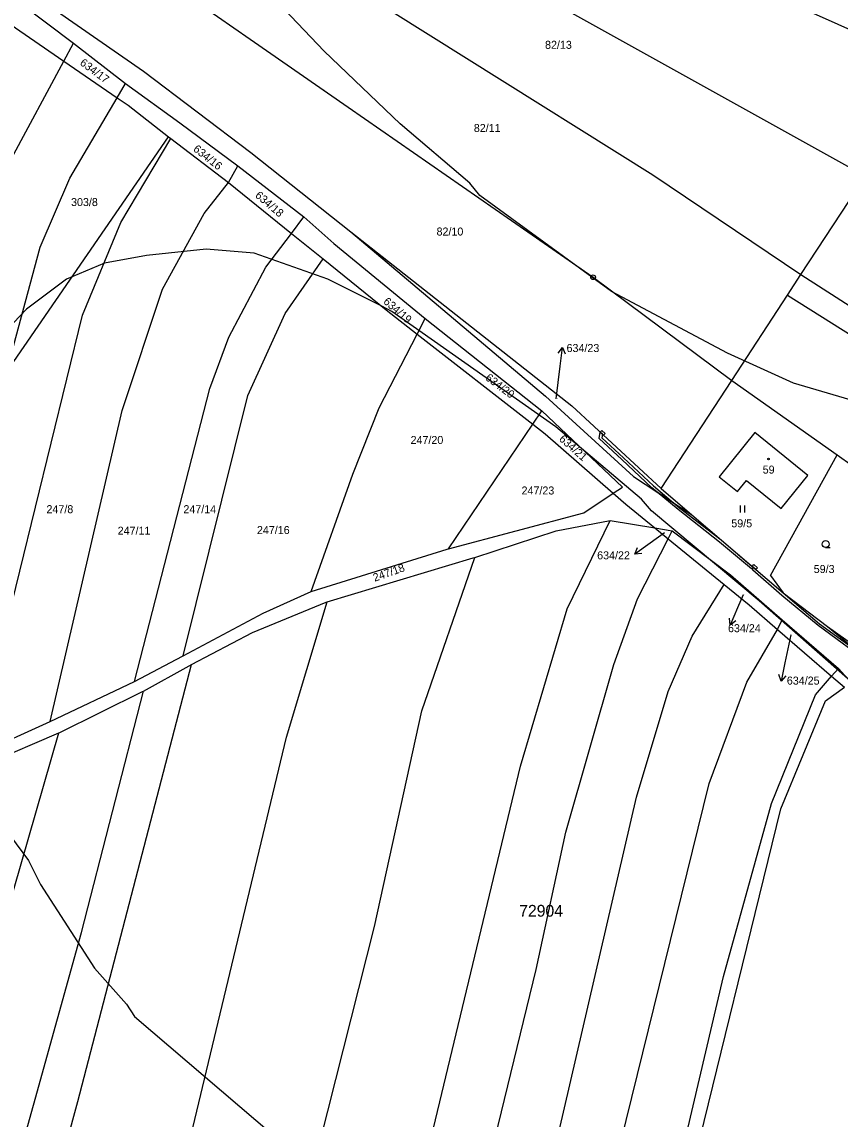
# Model space of a CAD drawing. Extents: x -743888 to -742027, y -1128394 to -1126768.
# Drawn here: x -743261.6 to -743087.8, y -1127789.2 to -1127556.1 of the extents above; entities that cross this region are included whole.
import ezdxf

# ---------------------------------------------------------------- set-up
doc = ezdxf.new("R2010")
doc.units = 0
for name, color, linetype in [('Vrstva 1', 7, 'Continuous'), ('Vrstva 16', 7, 'Continuous'), ('Vrstva 18', 7, 'Continuous'), ('Vrstva 19', 7, 'Continuous'), ('Vrstva 24', 7, 'Continuous'), ('Vrstva 25', 7, 'Continuous'), ('Vrstva 3', 7, 'Continuous'), ('Vrstva 30', 7, 'Continuous'), ('Vrstva 37', 7, 'Continuous'), ('Vrstva 4', 7, 'Continuous'), ('Vrstva 52', 7, 'Continuous'), ('Vrstva 53', 7, 'Continuous'), ('Vrstva 6', 7, 'Continuous')]:
    doc.layers.add(name, color=color, linetype=linetype)

msp = doc.modelspace()

# ---------------------------------------------------------------- linework, layer by layer
at = {"layer": 'Vrstva 1'}
for p, q in [((-743105.97, -1127643.33), (-743113.52, -1127652.75)), ((-743094.66, -1127652.45), (-743105.97, -1127643.33)), ((-743113.52, -1127652.75), (-743109.62, -1127655.89)), ((-743100.33, -1127659.49), (-743094.66, -1127652.45)), ((-743109.62, -1127655.89), (-743107.72, -1127653.53)), ((-743107.72, -1127653.53), (-743100.33, -1127659.49))]:
    msp.add_line(p, q, dxfattribs=at)
for points in [[(-743259.6, -1127550), (-743235.8, -1127566.59)], [(-743264.18, -1127556.62), (-743252.73, -1127564.48)], [(-743252.73, -1127564.48), (-743241.42, -1127572.24)], [(-743235.8, -1127566.59), (-743213.04, -1127583.89)], [(-743241.42, -1127572.24), (-743239.1, -1127573.83)], [(-743239.1, -1127573.83), (-743230.52, -1127580.51)], [(-743264.95, -1127630.5), (-743230.52, -1127580.51)], [(-743230.52, -1127580.51), (-743230.04, -1127580.88)], [(-743230.04, -1127580.88), (-743217.78, -1127590.26)], [(-743213.04, -1127583.89), (-743191.76, -1127600.69)], [(-743217.78, -1127590.26), (-743204.41, -1127601.05)], [(-743096.19, -1127609.82), (-743082.43, -1127588.87)], [(-743204.41, -1127601.05), (-743197.68, -1127606.48)], [(-743191.76, -1127600.69), (-743179.42, -1127610.43)], [(-743197.68, -1127606.48), (-743184.29, -1127617.28)], [(-743179.42, -1127610.43), (-743144.82, -1127637.7)], [(-743099.02, -1127614.17), (-743096.19, -1127609.82)], [(-743096.19, -1127609.82), (-743054.68, -1127636.42)], [(-743110.84, -1127632.34), (-743099.02, -1127614.17)], [(-743099.02, -1127614.17), (-743057.24, -1127640.46)], [(-743184.29, -1127617.28), (-743177.68, -1127622.43)], [(-743177.68, -1127622.43), (-743153.1, -1127641.6)], [(-743125.82, -1127655.26), (-743110.84, -1127632.34)], [(-743110.84, -1127632.34), (-743088.43, -1127648.09)], [(-743144.82, -1127637.7), (-743125.82, -1127655.26)], [(-743153.1, -1127641.6), (-743150.46, -1127643.66)], [(-743150.46, -1127643.66), (-743136.01, -1127656.26)], [(-743102.6, -1127673.7), (-743088.43, -1127648.09)], [(-743088.43, -1127648.09), (-743062.98, -1127666.21)], [(-743125.82, -1127655.26), (-743119.31, -1127660.83)], [(-743136.01, -1127656.26), (-743133.32, -1127658.6)], [(-743133.32, -1127658.6), (-743127.19, -1127663.61)], [(-743119.31, -1127660.83), (-743099.92, -1127677.43)], [(-743127.19, -1127663.61), (-743124.37, -1127665.91)], [(-743124.37, -1127665.91), (-743112.44, -1127675.65)], [(-743102.6, -1127673.7), (-743099.92, -1127677.43)], [(-743112.44, -1127675.65), (-743107.14, -1127679.98)], [(-743099.92, -1127677.43), (-743090.48, -1127684.56)], [(-743107.14, -1127679.98), (-743101.11, -1127685.19)], [(-743101.11, -1127685.19), (-743089.62, -1127695.12)], [(-743089.62, -1127695.12), (-743086.91, -1127697.47)]]:
    msp.add_lwpolyline(points, dxfattribs=at)
at = {"layer": 'Vrstva 16'}
for p, q in [((-743147.73, -1127626.47), (-743146.82, -1127625.27)), ((-743129.97, -1127669.03), (-743131.46, -1127669.18)), ((-743109.96, -1127683.35), (-743111.16, -1127684.25)), ((-743099.35, -1127695.06), (-743100.35, -1127696.18))]:
    msp.add_line(p, q, dxfattribs=at)
for points in [[(-743147.31, -1127629.24), (-743146.82, -1127625.27), (-743146.24, -1127626.65)], [(-743148.16, -1127636.21), (-743147.31, -1127629.24)], [(-743125.15, -1127664.66), (-743128.21, -1127666.85)], [(-743128.21, -1127666.85), (-743131.46, -1127669.18), (-743130.84, -1127667.81)], [(-743108.42, -1127677.83), (-743109.59, -1127680.57)], [(-743109.59, -1127680.57), (-743111.16, -1127684.25), (-743111.34, -1127682.76)], [(-743098.31, -1127686.3), (-743099.54, -1127692.26)], [(-743099.54, -1127692.26), (-743100.35, -1127696.18), (-743100.82, -1127694.75)]]:
    msp.add_lwpolyline(points, dxfattribs=at)
at = {"layer": 'Vrstva 24'}
msp.add_line((-743140.37, -1127610.37), (-743140.27, -1127610.37), dxfattribs=at)
msp.add_circle((-743140.32, -1127610.37), 0.499, dxfattribs=at)
at = {"layer": 'Vrstva 25'}
for p, q in [((-743109.07, -1127658.83), (-743109.07, -1127660.33)), ((-743108.07, -1127660.33), (-743108.07, -1127658.83)), ((-743090.91, -1127667.8), (-743089.91, -1127667.8))]:
    msp.add_line(p, q, dxfattribs=at)
for centre, radius in [((-743103.04, -1127648.98), 0.175), ((-743090.91, -1127667.05), 0.75)]:
    msp.add_circle(centre, radius, dxfattribs=at)
at = {"layer": 'Vrstva 3'}
for points in [[(-743105.97, -1127643.33), (-743113.52, -1127652.75)], [(-743094.66, -1127652.45), (-743105.97, -1127643.33)], [(-743113.52, -1127652.75), (-743109.62, -1127655.89)], [(-743100.33, -1127659.49), (-743094.66, -1127652.45)], [(-743109.62, -1127655.89), (-743107.72, -1127653.53)], [(-743107.72, -1127653.53), (-743100.33, -1127659.49)]]:
    msp.add_lwpolyline(points, dxfattribs=at)
at = {"layer": 'Vrstva 30'}
for points in [[(-743139.04, -1127644.65), (-743138.79, -1127643.27), (-743138.28, -1127643.74), (-743138.48, -1127644.49), (-743133.83, -1127648.71), (-743127.46, -1127654.69), (-743123.24, -1127658.26), (-743126.67, -1127656.02), (-743127.8, -1127655.07), (-743134.17, -1127649.07), (-743139.04, -1127644.65)], [(-743138.79, -1127643.27), (-743138.45, -1127642.9), (-743137.72, -1127643.58), (-743138.06, -1127643.95), (-743138.28, -1127643.74), (-743138.79, -1127643.27)], [(-743122.26, -1127659.74), (-743126.67, -1127656.02), (-743123.24, -1127658.26), (-743121.94, -1127659.36), (-743113.07, -1127666.17), (-743106.5, -1127671.8), (-743105.74, -1127672.45), (-743099.92, -1127677.43), (-743092.17, -1127683.97), (-743083.13, -1127690.59), (-743077.63, -1127695.11), (-743080.91, -1127692.83), (-743092.47, -1127684.37), (-743100.18, -1127677.94), (-743106.35, -1127672.62), (-743106.35, -1127672.32), (-743106.65, -1127672.28), (-743113.44, -1127666.65), (-743122.26, -1127659.74)], [(-743106.5, -1127671.8), (-743106.17, -1127671.42), (-743105.41, -1127672.07), (-743105.74, -1127672.45), (-743106.5, -1127671.8)]]:
    msp.add_lwpolyline(points, dxfattribs=at)
at = {"layer": 'Vrstva 37'}
msp.add_circle((-743103.04, -1127648.98), 0.175, dxfattribs=at)
at = {"layer": 'Vrstva 4'}
msp.add_lwpolyline([(-743090.48, -1127684.56), (-743072.72, -1127697.13)], dxfattribs=at)
at = {"layer": 'Vrstva 52'}
for points in [[(-743074.88, -1127639.63), (-743097.75, -1127632.88), (-743111.75, -1127626.5), (-743136.38, -1127613.38), (-743164.38, -1127593), (-743166.5, -1127590.38), (-743181.31, -1127577.75), (-743197.44, -1127562.38), (-743210.19, -1127548.88)], [(-743053.67, -1127722.32), (-743058.31, -1127718.5), (-743079.93, -1127701.11), (-743080.38, -1127700.75), (-743105, -1127679.13), (-743127.88, -1127660), (-743130, -1127657.5), (-743148.25, -1127642.13), (-743183.06, -1127617.63), (-743185.22, -1127616.53), (-743196.63, -1127610.75), (-743212.31, -1127605.25), (-743222.5, -1127604.38), (-743235.19, -1127605.75), (-743244.13, -1127607.38), (-743252.19, -1127610.75), (-743260.69, -1127617.13), (-743270.44, -1127627.38), (-743275.94, -1127635), (-743280.63, -1127645.13), (-743281.88, -1127655.38), (-743283.19, -1127657.88), (-743283.56, -1127673.13), (-743282.53, -1127677.41)], [(-743264.06, -1127729.13), (-743260.25, -1127734.25), (-743257.69, -1127739.38), (-743246.25, -1127757.13), (-743239.44, -1127764.75), (-743237.75, -1127767.38), (-743208.06, -1127792.75)]]:
    msp.add_lwpolyline(points, dxfattribs=at)
at = {"layer": 'Vrstva 6'}
for points in [[(-743239.89, -1127501.37), (-743082.43, -1127588.87)], [(-743246.36, -1127514.17), (-743127.6, -1127588.59)], [(-743254.82, -1127530.84), (-743140.32, -1127610.37)], [(-743113.85, -1127545.15), (-743067.95, -1127565.66)], [(-743262.15, -1127552), (-743250.66, -1127560.62)], [(-743252.73, -1127564.48), (-743250.66, -1127560.62)], [(-743250.66, -1127560.62), (-743239.62, -1127569.19)], [(-743263.84, -1127585.18), (-743252.73, -1127564.48)], [(-743241.42, -1127572.24), (-743239.62, -1127569.19)], [(-743239.62, -1127569.19), (-743228.08, -1127577.6)], [(-743251.48, -1127589.3), (-743241.42, -1127572.24)], [(-743228.08, -1127577.6), (-743215.78, -1127586.74)], [(-743240.66, -1127598.71), (-743230.04, -1127580.88)], [(-743217.78, -1127590.26), (-743215.78, -1127586.74)], [(-743215.78, -1127586.74), (-743201.77, -1127597.55)], [(-743257.74, -1127603.98), (-743251.48, -1127589.3)], [(-743222.92, -1127596.81), (-743217.78, -1127590.26)], [(-743127.6, -1127588.59), (-743096.19, -1127609.82)], [(-743231.77, -1127612.89), (-743222.92, -1127596.81)], [(-743248.78, -1127618.41), (-743240.66, -1127598.71)], [(-743204.41, -1127601.05), (-743201.77, -1127597.55)], [(-743201.77, -1127597.55), (-743195.41, -1127603.21)], [(-743209.85, -1127608.23), (-743204.41, -1127601.05)], [(-743191.76, -1127600.69), (-743150.41, -1127635.6)], [(-743264.95, -1127630.5), (-743257.74, -1127603.98)], [(-743195.41, -1127603.21), (-743175.98, -1127619.13)], [(-743205.71, -1127618.08), (-743197.68, -1127606.48)], [(-743217.66, -1127623.08), (-743209.85, -1127608.23)], [(-743140.32, -1127610.37), (-743110.84, -1127632.34)], [(-743240.36, -1127638.68), (-743231.77, -1127612.89)], [(-743213.64, -1127635.49), (-743205.71, -1127618.08)], [(-743265.43, -1127686.37), (-743248.78, -1127618.41)], [(-743177.68, -1127622.43), (-743175.98, -1127619.13)], [(-743175.98, -1127619.13), (-743151.19, -1127638.77)], [(-743185.76, -1127638.12), (-743177.68, -1127622.43)], [(-743221.74, -1127634), (-743217.66, -1127623.08)], [(-743237.76, -1127696.22), (-743221.74, -1127634)], [(-743227.38, -1127690.77), (-743213.64, -1127635.49)], [(-743150.41, -1127635.6), (-743131.7, -1127652.73)], [(-743255.66, -1127704.74), (-743240.36, -1127638.68)], [(-743191.34, -1127652.2), (-743185.76, -1127638.12)], [(-743153.1, -1127641.6), (-743151.19, -1127638.77)], [(-743151.19, -1127638.77), (-743134.07, -1127654.97)], [(-743170.99, -1127668.05), (-743153.1, -1127641.6)], [(-743200.21, -1127677.12), (-743191.34, -1127652.2)], [(-743131.7, -1127652.73), (-743119.31, -1127660.83)], [(-743136.01, -1127656.26), (-743134.07, -1127654.97)], [(-743142.28, -1127660.44), (-743136.01, -1127656.26)], [(-743170.99, -1127668.05), (-743142.28, -1127660.44)], [(-743148.15, -1127664.23), (-743136.68, -1127662.01)], [(-743145.81, -1127680.82), (-743136.68, -1127662.01)], [(-743136.68, -1127662.01), (-743127.19, -1127663.61)], [(-743165.44, -1127669.87), (-743148.15, -1127664.23)], [(-743127.19, -1127663.61), (-743123.51, -1127664.23)], [(-743124.37, -1127665.91), (-743123.51, -1127664.23)], [(-743123.51, -1127664.23), (-743111.14, -1127673.56)], [(-743130.84, -1127678.65), (-743124.37, -1127665.91)], [(-743200.21, -1127677.12), (-743171.32, -1127668.14)], [(-743171.32, -1127668.14), (-743170.99, -1127668.05)], [(-743196.8, -1127679.29), (-743165.75, -1127669.97)], [(-743176.72, -1127702.48), (-743165.44, -1127669.87)], [(-743165.75, -1127669.97), (-743165.44, -1127669.87)], [(-743111.14, -1127673.56), (-743100.14, -1127683.11)], [(-743119.23, -1127686.62), (-743112.44, -1127675.65)], [(-743210.43, -1127681.71), (-743200.21, -1127677.12)], [(-743135.93, -1127692.62), (-743130.84, -1127678.65)], [(-743212.68, -1127685.82), (-743197.04, -1127679.36)], [(-743205.44, -1127708.1), (-743196.8, -1127679.29)], [(-743197.04, -1127679.36), (-743196.8, -1127679.29)], [(-743155.72, -1127714.23), (-743145.81, -1127680.82)], [(-743227.38, -1127690.77), (-743210.43, -1127681.71)], [(-743101.11, -1127685.19), (-743100.14, -1127683.11)], [(-743100.14, -1127683.11), (-743088.2, -1127693.47)], [(-743107.65, -1127696.37), (-743101.11, -1127685.19)], [(-743090.48, -1127684.56), (-743071.53, -1127700.11)], [(-743225.59, -1127692.63), (-743212.68, -1127685.82)], [(-743124.32, -1127698.36), (-743119.23, -1127686.62)], [(-743249.75, -1127785.46), (-743225.59, -1127692.63)], [(-743237.76, -1127696.22), (-743227.5, -1127690.84)], [(-743227.5, -1127690.84), (-743227.38, -1127690.77)], [(-743226.1, -1127692.9), (-743225.59, -1127692.63)], [(-743146.1, -1127728.25), (-743135.93, -1127692.62)], [(-743235.82, -1127698.28), (-743226.1, -1127692.9)], [(-743093.02, -1127699.07), (-743089.62, -1127695.12)], [(-743089.62, -1127695.12), (-743088.2, -1127693.47)], [(-743088.2, -1127693.47), (-743085.48, -1127696.45)], [(-743255.66, -1127704.74), (-743237.76, -1127696.22)], [(-743115.61, -1127717.91), (-743107.65, -1127696.37)], [(-743253.75, -1127707.12), (-743236.01, -1127698.38)], [(-743249, -1127749.54), (-743235.82, -1127698.28)], [(-743236.01, -1127698.38), (-743235.82, -1127698.28)], [(-743131.1, -1127720.81), (-743124.32, -1127698.36)], [(-743102.39, -1127722.13), (-743093.02, -1127699.07)], [(-743090.95, -1127700.36), (-743086.91, -1127697.47)], [(-743100.45, -1127723.29), (-743090.95, -1127700.36)], [(-743186.75, -1127748.28), (-743176.72, -1127702.48)], [(-743270.64, -1127711.51), (-743255.66, -1127704.74)], [(-743268.66, -1127713.55), (-743253.81, -1127707.15)], [(-743266.62, -1127751.47), (-743253.81, -1127707.15)], [(-743253.81, -1127707.15), (-743253.75, -1127707.12)], [(-743227.42, -1127799.64), (-743205.44, -1127708.1)], [(-743186.13, -1127840.64), (-743155.72, -1127714.23)], [(-743140.31, -1127817.95), (-743115.61, -1127717.91)], [(-743166.85, -1127875.07), (-743131.1, -1127720.81)], [(-743112.61, -1127758.91), (-743102.39, -1127722.13)], [(-743120.32, -1127804.45), (-743100.45, -1127723.29)], [(-743152.4, -1127757.44), (-743146.1, -1127728.25)], [(-743204.89, -1127820), (-743186.75, -1127748.28)], [(-743300.05, -1127932.95), (-743249, -1127749.54)], [(-743177.21, -1127859.16), (-743152.4, -1127757.44)], [(-743139.42, -1127873.34), (-743112.61, -1127758.91)], [(-743287.33, -1127923.2), (-743249.75, -1127785.46)]]:
    msp.add_lwpolyline(points, dxfattribs=at)

# ---------------------------------------------------------------- texts
at = {"layer": 'Vrstva 16'}
for s, p in [('634/23', (-743145.94, -1127626.26)), ('634/22', (-743139.44, -1127670.29)), ('634/24', (-743111.64, -1127685.77)), ('634/25', (-743099.14, -1127696.9))]:
    msp.add_text(s, height=1.7, dxfattribs=at).set_placement(p)
at = {"layer": 'Vrstva 18'}
for s, height, p in [('82/13', 1.7, (-743150.51, -1127561.85)), ('82/11', 1.7, (-743165.64, -1127579.52)), ('303/8', 1.7, (-743251.21, -1127595.25)), ('82/10', 1.7, (-743173.56, -1127601.51)), ('634/23', 0.1, (-743148.16, -1127636.21)), ('247/20', 1.7, (-743179.08, -1127645.79)), ('247/23', 1.7, (-743155.5, -1127656.52)), ('247/8', 1.7, (-743256.43, -1127660.49)), ('247/14', 1.7, (-743227.34, -1127660.49)), ('59/5', 1.7, (-743110.94, -1127663.49)), ('247/11', 1.7, (-743241.31, -1127665.06)), ('247/16', 1.7, (-743211.72, -1127664.92)), ('634/22', 0.1, (-743125.15, -1127664.66)), ('59/3', 1.7, (-743093.43, -1127673.2)), ('634/24', 0.1, (-743108.42, -1127677.83)), ('634/25', 0.1, (-743098.31, -1127686.3))]:
    msp.add_text(s, height=height, dxfattribs=at).set_placement(p)
for s, rotation, p in [('634/17', 323.1724, (-743249.48, -1127565.12)), ('634/16', 321.5463, (-743225.4, -1127583.4)), ('634/18', 319.4608, (-743212.24, -1127593.21)), ('634/19', 319.1308, (-743185.01, -1127615.76)), ('634/20', 322.8323, (-743163.35, -1127632.02)), ('634/21', 318.3664, (-743147.68, -1127644.93)), ('247/18', 19.4485, (-743186.71, -1127675.06))]:
    msp.add_text(s, height=1.7, rotation=rotation, dxfattribs=at).set_placement(p)
at = {"layer": 'Vrstva 19'}
msp.add_text('59', height=1.7, dxfattribs=at).set_placement((-743104.27, -1127652.08))
at = {"layer": 'Vrstva 53'}
msp.add_text('72904', height=2.5, dxfattribs=at).set_placement((-743156, -1127746.2))

doc.saveas('drawing.dxf')
